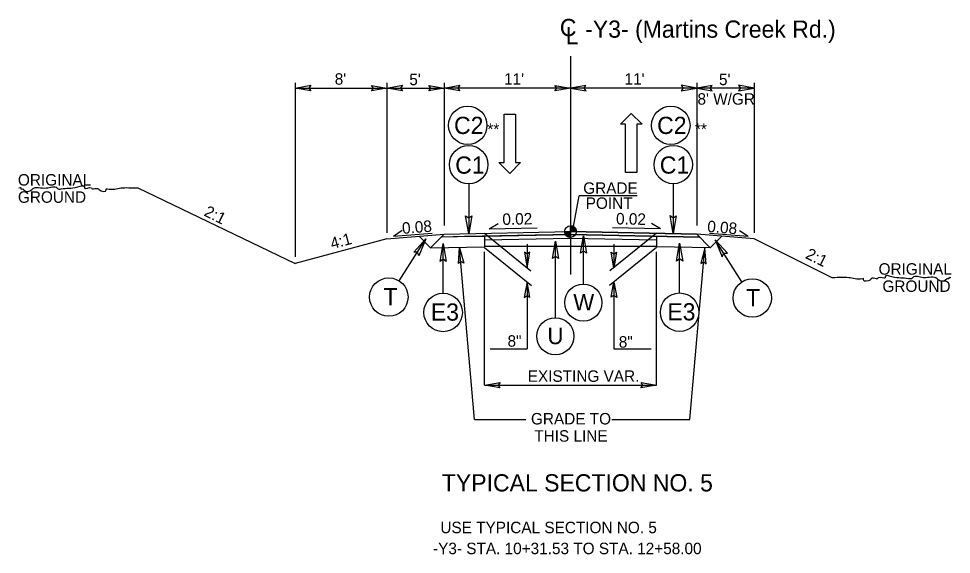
# Model space of a CAD drawing. Extents: x 18938 to 19565, y 6931 to 7973.
# Drawn here: x 19398 to 19479.3, y 7598.2 to 7644.9 of the extents above; entities that cross this region are included whole.
import ezdxf

# ---------------------------------------------------------------- set-up
doc = ezdxf.new("R2010")
doc.units = 0
for name, color, linetype in [('Old_Level_11', 7, 'Continuous'), ('Old_Level_2', 7, 'Continuous'), ('Prop Pavement Schedule Description CELL', 7, 'Continuous'), ('Prop Shade Medium', 7, 'Continuous'), ('Prop Terminator CELL', 7, 'Continuous'), ('Sheet Data Field CELL', 7, 'Continuous'), ('Sheet Plot Border Outside CELL', 7, 'Continuous'), ('Sheet Typical CELL', 7, 'Continuous'), ('Typical Curb CELL', 7, 'Continuous'), ('Typical Detail Wedge1 CELL', 7, 'Continuous'), ('Typical Detail Wedge2 CELL', 7, 'Continuous'), ('Typical Detail Wedge3 CELL', 7, 'Continuous'), ('Typical Hinge Slope Arterial CELL', 7, 'Continuous'), ('Typical ID Circle CELL', 7, 'Continuous'), ('Typical Shoulder Slope Information CELL', 7, 'Continuous'), ('Typical Terminator CELL', 7, 'Continuous'), ('Typical Text General CELL', 7, 'Continuous'), ('Typical Text Grade Point CELL', 7, 'Continuous'), ('Typical Text ID Circle CELL', 7, 'Continuous'), ('Typical Text Label CELL', 7, 'Continuous')]:
    doc.layers.add(name, color=color, linetype=linetype)

msp = doc.modelspace()

# ---------------------------------------------------------------- linework, layer by layer
at = {"layer": 'Prop Pavement Schedule Description CELL'}
for p, q in [((19430.073, 7625.727), (19435.073, 7626.127)), ((19433.882, 7624.936), (19432.868, 7625.95)), ((19433.882, 7624.936), (19435.073, 7626.127)), ((19446.073, 7626.097), (19434.818, 7625.872)), ((19435.073, 7626.127), (19446.073, 7626.347)), ((19437.073, 7625.917), (19446.073, 7626.097)), ((19457.073, 7626.127), (19446.072, 7626.347)), ((19446.073, 7626.097), (19457.328, 7625.872)), ((19462.073, 7625.727), (19457.073, 7626.127)), ((19458.263, 7624.936), (19457.073, 7626.127)), ((19458.263, 7624.936), (19459.277, 7625.95)), ((19468.874, 7622.326), (19462.073, 7625.727)), ((19433.882, 7624.936), (19438.573, 7625.03)), ((19438.573, 7625.034), (19438.573, 7625.03)), ((19453.573, 7625.034), (19453.573, 7625.03)), ((19458.263, 7624.936), (19453.573, 7625.03))]:
    msp.add_line(p, q, dxfattribs=at)
at = {"layer": 'Prop Shade Medium'}
for p in [(19408.339, 7630.147), (19430.073, 7625.727)]:
    msp.add_line(p, (19422.073, 7623.578), dxfattribs=at)
at = {"layer": 'Sheet Data Field CELL'}
for points in [[(19423.423, 7638.619), (19422.073, 7638.852), (19423.43, 7639.092), (19423.258, 7638.852)], [(19428.723, 7639.084), (19430.073, 7638.852), (19428.715, 7638.612), (19428.888, 7638.852)], [(19431.423, 7638.619), (19430.073, 7638.852), (19431.43, 7639.092), (19431.258, 7638.852)], [(19433.723, 7639.084), (19435.073, 7638.852), (19433.715, 7638.612), (19433.888, 7638.852)], [(19436.423, 7638.619), (19435.073, 7638.852), (19436.43, 7639.092), (19436.258, 7638.852)], [(19444.721, 7639.084), (19446.071, 7638.852), (19444.713, 7638.612), (19444.886, 7638.852)], [(19447.421, 7639.084), (19446.071, 7638.852), (19447.428, 7638.612), (19447.256, 7638.852)], [(19455.723, 7638.619), (19457.073, 7638.852), (19455.715, 7639.092), (19455.888, 7638.852)], [(19458.423, 7639.084), (19457.073, 7638.852), (19458.43, 7638.612), (19458.258, 7638.852)], [(19460.723, 7638.619), (19462.073, 7638.852), (19460.715, 7639.092), (19460.888, 7638.852)], [(19436.295, 7623.552), (19436.41, 7624.917), (19436.766, 7623.585), (19436.512, 7623.737)], [(19442.049, 7624.542), (19442.282, 7623.192), (19442.522, 7624.55), (19442.282, 7624.377)], [(19450.096, 7624.542), (19449.863, 7623.192), (19449.623, 7624.55), (19449.863, 7624.377)], [(19457.903, 7623.526), (19457.788, 7624.891), (19457.431, 7623.559), (19457.685, 7623.71)], [(19442.514, 7620.619), (19442.282, 7621.969), (19442.042, 7620.611), (19442.282, 7620.784)], [(19449.631, 7620.619), (19449.864, 7621.969), (19450.104, 7620.611), (19449.864, 7620.784)], [(19439.923, 7612.733), (19438.573, 7612.965), (19439.93, 7613.205), (19439.758, 7612.965)], [(19452.223, 7613.198), (19453.573, 7612.965), (19452.215, 7612.725), (19452.388, 7612.965)]]:
    msp.add_lwpolyline(points, close=True, dxfattribs=at)
at = {"layer": 'Sheet Typical CELL'}
for p, q in [((19422.073, 7639.312), (19422.073, 7624.147)), ((19422.073, 7638.852), (19430.073, 7638.852)), ((19430.073, 7639.312), (19430.073, 7626.224)), ((19430.073, 7638.852), (19435.073, 7638.852)), ((19435.073, 7639.312), (19435.073, 7626.867)), ((19457.073, 7638.852), (19435.073, 7638.852)), ((19457.073, 7639.312), (19457.073, 7626.867)), ((19462.073, 7638.852), (19457.073, 7638.852)), ((19462.073, 7639.312), (19462.073, 7626.224)), ((19438.573, 7626.197), (19442.628, 7622.912)), ((19453.573, 7626.197), (19449.517, 7622.912)), ((19437.702, 7609.965), (19436.41, 7624.917)), ((19438.573, 7624.973), (19442.678, 7621.648)), ((19442.282, 7625.236), (19442.282, 7623.192)), ((19453.573, 7624.973), (19449.468, 7621.648)), ((19449.863, 7625.236), (19449.863, 7623.192)), ((19438.573, 7612.965), (19438.573, 7624.59)), ((19453.573, 7612.965), (19453.573, 7624.59)), ((19456.484, 7609.965), (19457.788, 7624.891)), ((19442.282, 7621.969), (19442.282, 7616.131)), ((19449.864, 7621.969), (19449.864, 7616.131)), ((19439.057, 7616.131), (19442.282, 7616.131)), ((19449.864, 7616.131), (19453.116, 7616.131)), ((19438.573, 7612.965), (19453.573, 7612.965)), ((19437.702, 7609.965), (19442.19, 7609.965)), ((19449.668, 7609.965), (19456.484, 7609.965))]:
    msp.add_line(p, q, dxfattribs=at)
at = {"layer": 'Typical Curb CELL'}
for points in [[(19397.975, 7630.147), (19398.146, 7630.147), (19398.146, 7630.062), (19398.318, 7630.062), (19398.403, 7629.976), (19399.089, 7629.976), (19399.174, 7630.062), (19400.374, 7630.147), (19401.316, 7630.147), (19401.401, 7630.062), (19401.658, 7630.062), (19403.114, 7630.233), (19403.714, 7630.233), (19403.714, 7630.147), (19404.313, 7630.147), (19404.399, 7630.062), (19404.485, 7630.062), (19404.913, 7630.062), (19404.999, 7629.976), (19405.598, 7629.976), (19405.598, 7630.062), (19405.684, 7630.062), (19406.883, 7630.147), (19408.254, 7630.147), (19408.339, 7630.147)], [(19479.238, 7622.326), (19479.067, 7622.326), (19479.067, 7622.24), (19478.896, 7622.24), (19478.81, 7622.155), (19478.124, 7622.155), (19478.039, 7622.24), (19476.84, 7622.326), (19475.898, 7622.326), (19475.812, 7622.24), (19475.555, 7622.24), (19474.099, 7622.412), (19473.499, 7622.412), (19473.499, 7622.326), (19472.9, 7622.326), (19472.814, 7622.24), (19472.728, 7622.24), (19472.3, 7622.24), (19472.214, 7622.155), (19471.615, 7622.155), (19471.615, 7622.24), (19471.529, 7622.24), (19470.33, 7622.326), (19468.96, 7622.326), (19468.874, 7622.326)]]:
    msp.add_spline(points, degree=3, dxfattribs=at)
at = {"layer": 'Typical Detail Wedge1 CELL'}
for p, q in [((19446.073, 7626.347), (19446.073, 7626.859)), ((19445.561, 7626.347), (19446.073, 7626.347)), ((19446.072, 7625.834), (19446.073, 7626.347)), ((19446.073, 7626.347), (19446.072, 7625.834)), ((19446.585, 7626.347), (19446.073, 7626.347))]:
    msp.add_line(p, q, dxfattribs=at)
for points in [[(19446.078, 7626.859), (19446.078, 7626.859), (19446.078, 7626.347)], [(19446.088, 7626.858), (19446.088, 7626.347)], [(19446.098, 7626.858), (19446.098, 7626.347)], [(19446.109, 7626.857), (19446.108, 7626.347)], [(19446.119, 7626.856), (19446.119, 7626.347)], [(19446.129, 7626.856), (19446.129, 7626.347)], [(19446.139, 7626.854), (19446.139, 7626.347)], [(19446.149, 7626.853), (19446.149, 7626.347)], [(19446.16, 7626.851), (19446.159, 7626.347)], [(19446.17, 7626.849), (19446.17, 7626.347)], [(19446.18, 7626.847), (19446.18, 7626.347)], [(19446.19, 7626.845), (19446.19, 7626.347)], [(19446.201, 7626.842), (19446.201, 7626.347)], [(19446.211, 7626.839), (19446.211, 7626.347)], [(19446.221, 7626.837), (19446.221, 7626.347)], [(19446.231, 7626.834), (19446.231, 7626.347)], [(19446.242, 7626.83), (19446.242, 7626.347)], [(19446.252, 7626.826), (19446.252, 7626.347)], [(19446.262, 7626.822), (19446.262, 7626.347)], [(19446.273, 7626.818), (19446.272, 7626.347)], [(19446.283, 7626.813), (19446.283, 7626.347)], [(19446.293, 7626.809), (19446.293, 7626.347)], [(19446.303, 7626.804), (19446.303, 7626.347)], [(19446.313, 7626.798), (19446.313, 7626.347)], [(19446.324, 7626.793), (19446.323, 7626.347)], [(19446.334, 7626.787), (19446.334, 7626.347)], [(19446.344, 7626.781), (19446.344, 7626.347)], [(19446.354, 7626.774), (19446.354, 7626.347)], [(19446.364, 7626.767), (19446.364, 7626.347)], [(19446.375, 7626.76), (19446.375, 7626.347)], [(19446.385, 7626.752), (19446.385, 7626.347)], [(19446.395, 7626.744), (19446.395, 7626.347)], [(19446.405, 7626.736), (19446.405, 7626.347)], [(19446.416, 7626.726), (19446.416, 7626.346)], [(19446.426, 7626.717), (19446.426, 7626.347)], [(19446.436, 7626.707), (19446.436, 7626.346)], [(19446.447, 7626.697), (19446.447, 7626.346)], [(19446.457, 7626.685), (19446.457, 7626.347)], [(19446.467, 7626.673), (19446.467, 7626.346)], [(19446.477, 7626.66), (19446.477, 7626.346)], [(19446.488, 7626.647), (19446.487, 7626.347)], [(19446.498, 7626.632), (19446.498, 7626.346)], [(19446.508, 7626.616), (19446.508, 7626.346)], [(19446.518, 7626.599), (19446.518, 7626.347)], [(19446.528, 7626.58), (19446.528, 7626.346)], [(19446.539, 7626.559), (19446.538, 7626.346)], [(19446.549, 7626.535), (19446.549, 7626.347)], [(19445.564, 7626.347), (19445.564, 7626.291)], [(19445.574, 7626.347), (19445.574, 7626.231)], [(19445.584, 7626.347), (19445.584, 7626.193)], [(19445.595, 7626.347), (19445.595, 7626.164)], [(19445.605, 7626.347), (19445.605, 7626.139)], [(19445.615, 7626.347), (19445.615, 7626.117)], [(19445.625, 7626.347), (19445.625, 7626.098)], [(19445.635, 7626.347), (19445.635, 7626.081)], [(19445.646, 7626.347), (19445.646, 7626.064)], [(19445.656, 7626.347), (19445.656, 7626.049)], [(19445.666, 7626.347), (19445.666, 7626.036)], [(19445.676, 7626.347), (19445.676, 7626.023)], [(19445.686, 7626.347), (19445.686, 7626.01)], [(19445.697, 7626.347), (19445.697, 7625.999)], [(19445.707, 7626.347), (19445.707, 7625.988)], [(19445.717, 7626.347), (19445.717, 7625.978)], [(19445.727, 7626.347), (19445.727, 7625.969)], [(19445.738, 7626.347), (19445.738, 7625.96)], [(19445.748, 7626.347), (19445.748, 7625.951)], [(19445.758, 7626.347), (19445.758, 7625.942)], [(19445.769, 7626.347), (19445.769, 7625.935)], [(19445.779, 7626.347), (19445.779, 7625.927)], [(19445.789, 7626.347), (19445.789, 7625.92)], [(19445.799, 7626.347), (19445.799, 7625.914)], [(19445.81, 7626.347), (19445.809, 7625.907)], [(19445.82, 7626.347), (19445.82, 7625.901)], [(19445.83, 7626.347), (19445.83, 7625.896)], [(19445.84, 7626.347), (19445.84, 7625.89)], [(19445.85, 7626.347), (19445.85, 7625.885)], [(19445.861, 7626.347), (19445.86, 7625.881)], [(19445.871, 7626.347), (19445.871, 7625.876)], [(19445.881, 7626.347), (19445.881, 7625.872)], [(19445.891, 7626.347), (19445.891, 7625.868)], [(19445.902, 7626.347), (19445.902, 7625.864)], [(19445.912, 7626.347), (19445.912, 7625.86)], [(19445.922, 7626.347), (19445.922, 7625.857)], [(19445.932, 7626.347), (19445.932, 7625.854)], [(19445.943, 7626.347), (19445.943, 7625.851)], [(19445.953, 7626.347), (19445.953, 7625.849)], [(19445.963, 7626.347), (19445.963, 7625.846)], [(19445.973, 7626.347), (19445.973, 7625.844)], [(19445.984, 7626.347), (19445.984, 7625.843)], [(19445.994, 7626.347), (19445.994, 7625.841)], [(19446.004, 7626.347), (19446.004, 7625.839)], [(19446.014, 7626.347), (19446.014, 7625.838)], [(19446.025, 7626.347), (19446.024, 7625.837)], [(19446.035, 7626.347), (19446.035, 7625.836)], [(19446.045, 7626.347), (19446.045, 7625.836)], [(19446.055, 7626.347), (19446.055, 7625.835)], [(19446.065, 7626.347), (19446.065, 7625.834), (19446.065, 7625.834)], [(19446.559, 7626.506), (19446.559, 7626.346)], [(19446.569, 7626.471), (19446.569, 7626.346)], [(19446.579, 7626.419), (19446.579, 7626.347)]]:
    msp.add_lwpolyline(points, dxfattribs=at)
msp.add_circle((19446.073, 7626.347), 0.512, dxfattribs=at)
for start, end in [(359.99048, 89.99048), (179.99048, 269.99048)]:
    msp.add_arc((19446.073, 7626.347), 0.512, start, end, dxfattribs=at)
at = {"layer": 'Typical Detail Wedge3 CELL'}
for p, q in [((19440.28, 7632.365), (19440.28, 7636.565)), ((19440.28, 7636.565), (19441.27, 7636.565)), ((19441.27, 7636.565), (19441.27, 7632.365)), ((19450.426, 7635.694), (19451.356, 7636.639)), ((19451.356, 7636.639), (19452.316, 7635.694)), ((19450.876, 7635.694), (19450.426, 7635.694)), ((19450.876, 7631.494), (19450.876, 7635.694)), ((19452.316, 7635.694), (19451.866, 7635.694)), ((19451.866, 7635.694), (19451.866, 7631.494)), ((19440.79, 7631.42), (19439.83, 7632.365)), ((19439.83, 7632.365), (19440.28, 7632.365)), ((19441.72, 7632.365), (19440.79, 7631.42)), ((19441.27, 7632.365), (19441.72, 7632.365)), ((19451.866, 7631.494), (19450.876, 7631.494))]:
    msp.add_line(p, q, dxfattribs=at)
at = {"layer": 'Typical Hinge Slope Arterial CELL'}
for p, q in [((19434.818, 7625.872), (19435.073, 7626.127)), ((19436.818, 7625.912), (19434.818, 7625.872)), ((19435.073, 7626.127), (19446.073, 7626.347)), ((19446.073, 7626.097), (19436.818, 7625.912)), ((19436.818, 7625.912), (19436.818, 7625.912)), ((19446.073, 7626.347), (19457.073, 7626.127)), ((19457.328, 7625.872), (19446.073, 7626.097)), ((19457.073, 7626.127), (19457.328, 7625.872))]:
    msp.add_line(p, q, dxfattribs=at)
at = {"layer": 'Typical ID Circle CELL'}
for p, q in [((19438.573, 7625.947), (19438.573, 7625.034)), ((19438.573, 7625.628), (19446.073, 7625.778)), ((19446.073, 7625.778), (19453.573, 7625.628)), ((19453.573, 7625.947), (19453.573, 7625.034)), ((19453.573, 7625.034), (19438.573, 7625.034))]:
    msp.add_line(p, q, dxfattribs=at)
at = {"layer": 'Typical Terminator CELL'}
for p, q in [((19437.196, 7630.503), (19437.196, 7626.172)), ((19455.032, 7630.508), (19455.032, 7626.177)), ((19447.196, 7621.778), (19447.196, 7625.962)), ((19431.135, 7622.053), (19433.462, 7625.706)), ((19434.97, 7620.973), (19434.97, 7625.305)), ((19444.753, 7618.845), (19444.753, 7625.498)), ((19455.584, 7620.996), (19455.584, 7625.327)), ((19461.022, 7621.968), (19458.695, 7625.621))]:
    msp.add_line(p, q, dxfattribs=at)
for centre, radius in [((19437.116, 7635.599), 1.676), ((19454.82, 7635.599), 1.676), ((19437.196, 7632.179), 1.676), ((19455.033, 7632.184), 1.676), ((19430.235, 7620.639), 1.676), ((19447.196, 7620.159), 1.619), ((19461.922, 7620.555), 1.676), ((19434.97, 7619.298), 1.676), ((19455.584, 7619.32), 1.676), ((19444.753, 7617.226), 1.619)]:
    msp.add_circle(centre, radius, dxfattribs=at)
at = {"layer": 'Typical Text General CELL'}
for points in [[(19437.463, 7627.723), (19437.196, 7626.172), (19436.92, 7627.732), (19437.196, 7627.534)], [(19455.3, 7627.729), (19455.032, 7626.177), (19454.757, 7627.737), (19455.032, 7627.539)], [(19446.938, 7624.463), (19447.196, 7625.962), (19447.462, 7624.455), (19447.196, 7624.646)], [(19432.403, 7624.54), (19433.462, 7625.706), (19432.856, 7624.241), (19432.73, 7624.557)], [(19434.702, 7623.753), (19434.97, 7625.305), (19435.246, 7623.744), (19434.97, 7623.942)], [(19444.495, 7623.999), (19444.753, 7625.498), (19445.02, 7623.991), (19444.753, 7624.183)], [(19455.317, 7623.775), (19455.584, 7625.327), (19455.86, 7623.766), (19455.584, 7623.965)], [(19459.754, 7624.456), (19458.695, 7625.621), (19459.301, 7624.157), (19459.427, 7624.473)]]:
    msp.add_lwpolyline(points, close=True, dxfattribs=at)
at = {"layer": 'Typical Text Grade Point CELL'}
for p, q in [((19438.977, 7626.587), (19439.76, 7627.06)), ((19438.977, 7626.587), (19443.166, 7626.671)), ((19453.921, 7626.587), (19449.732, 7626.671)), ((19453.921, 7626.587), (19453.138, 7627.06)), ((19430.64, 7625.947), (19431.393, 7626.467)), ((19430.64, 7625.947), (19434.026, 7626.218)), ((19461.571, 7625.903), (19458.185, 7626.174)), ((19461.571, 7625.903), (19460.818, 7626.423))]:
    msp.add_line(p, q, dxfattribs=at)
at = {"layer": 'Typical Text ID Circle CELL'}
for p, q in [((19446.073, 7641.641), (19446.073, 7638.311)), ((19446.073, 7638.311), (19446.073, 7622.61)), ((19446.323, 7626.8), (19446.818, 7629.468)), ((19451.895, 7629.467), (19446.818, 7629.468))]:
    msp.add_line(p, q, dxfattribs=at)

# ---------------------------------------------------------------- texts
at = {"layer": 'Old_Level_11'}
for s, height, p in [('TYPICAL SECTION NO. 5', 1.5, (19434.857, 7603.705)), ('USE TYPICAL SECTION NO. 5', 1, (19434.728, 7600.066))]:
    msp.add_text(s, height=height, dxfattribs=at).set_placement(p)
at = {"layer": 'Old_Level_2'}
for s, p in [('ORIGINAL', (19397.898, 7630.354)), ('GROUND', (19397.898, 7628.854))]:
    msp.add_text(s, height=1, rotation=360, dxfattribs=at).set_placement(p)
for s, p in [('ORIGINAL', (19472.931, 7622.59)), ('GROUND', (19473.267, 7621.09))]:
    msp.add_text(s, height=1, dxfattribs=at).set_placement(p)
at = {"layer": 'Prop Terminator CELL'}
for s, height, p in [('C2', 1.5, (19435.921, 7634.849)), ('C2', 1.5, (19453.625, 7634.849)), ('C1', 1.5, (19436.022, 7631.39)), ('C1', 1.5, (19453.859, 7631.395)), ('W', 1.449, (19446.316, 7619.472)), ('T', 1.5, (19461.377, 7619.835)), ('E3', 1.5, (19433.898, 7618.586)), ('E3', 1.5, (19454.512, 7618.608)), ('U', 1.449, (19444.058, 7616.539))]:
    msp.add_text(s, height=height, dxfattribs=at).set_placement(p)
msp.add_text('T', height=1.5, rotation=360, dxfattribs=at).set_placement((19429.766, 7619.919))
at = {"layer": 'Sheet Plot Border Outside CELL'}
for s, p in [('GRADE', (19447.183, 7629.636)), ('POINT', (19447.402, 7628.325))]:
    msp.add_text(s, height=1, rotation=0.00004, dxfattribs=at).set_placement(p)
at = {"layer": 'Typical Detail Wedge2 CELL'}
for s, p in [("8'", (19425.519, 7639.141)), ("5'", (19432.019, 7639.102)), ("11'", (19440.279, 7639.141)), ("11'", (19450.784, 7639.141)), ("5'", (19459.019, 7639.102)), ("8' W/GR", (19457.143, 7637.402)), ('**', (19438.824, 7634.766)), ('**', (19456.919, 7634.766)), ('8"', (19440.582, 7616.314)), ('8"', (19450.282, 7616.234)), ('EXISTING VAR.', (19442.344, 7613.255)), ('GRADE TO', (19442.626, 7609.54)), ('THIS LINE', (19442.917, 7608.04)), ('-Y3- STA. 10+31.53 TO STA. 12+58.00', (19434.088, 7598.239))]:
    msp.add_text(s, height=1, dxfattribs=at).set_placement(p)
at = {"layer": 'Typical Shoulder Slope Information CELL'}
for s, rotation, p in [('2:1', 333.43491, (19414.049, 7627.769)), ('4:1', 15.1346, (19425.288, 7624.803)), ('2:1', 333.43491, (19466.486, 7624.065))]:
    msp.add_text(s, height=1, rotation=rotation, dxfattribs=at).set_placement(p)
at = {"layer": 'Typical Text Grade Point CELL'}
for s, rotation, p in [('0.02', 1.14574, (19440.144, 7626.922)), ('0.02', 358.85426, (19450.036, 7626.976)), ('0.08', 4.5738, (19431.428, 7626.136)), ('0.08', 355.4262, (19457.967, 7626.317))]:
    msp.add_text(s, height=1, rotation=rotation, dxfattribs=at).set_placement(p)
at = {"layer": 'Typical Text Label CELL'}
for s, p in [('C', (19445.144, 7643.374)), ('-Y3- (Martins Creek Rd.)', (19447.352, 7643.236)), ('L', (19445.66, 7642.668))]:
    msp.add_text(s, height=1.5, dxfattribs=at).set_placement(p)

doc.saveas('drawing.dxf')
